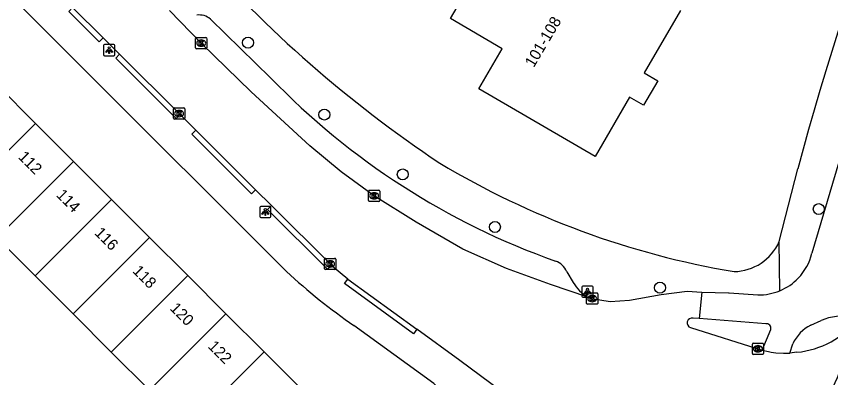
# Model space of a CAD drawing. Extents: x 159961 to 160856, y 382704 to 383353.
# Drawn here: x 160281.3 to 160353.9, y 383169.2 to 383201.5 of the extents above; entities that cross this region are included whole.
import ezdxf

# ---------------------------------------------------------------- set-up
doc = ezdxf.new("R2010")
doc.units = 0
for name, color, linetype in [('IMGEO_Boom', 7, 'Continuous'), ('IMGEO_Fietspad_open', 7, 'Continuous'), ('IMGEO_Kolk', 7, 'Continuous'), ('IMGEO_Lichtpunt', 7, 'Continuous'), ('IMGEO_Pand', 7, 'Continuous'), ('IMGEO_Pand_nummerreeks', 7, 'Continuous'), ('IMGEO_Rijbaan_lokaal_gesloten', 7, 'Continuous'), ('IMGEO_Rijbaan_lokaal_open', 7, 'Continuous'), ('IMGEO_Voetpad_open', 7, 'Continuous')]:
    doc.layers.add(name, color=color, linetype=linetype)

msp = doc.modelspace()

# ---------------------------------------------------------------- linework, layer by layer
at = {"layer": 'IMGEO_Boom'}
for centre in [(160301.954, 383199.113), (160308.756, 383192.694), (160315.74, 383187.359), (160352.813, 383184.261), (160323.955, 383182.666), (160338.661, 383177.252)]:
    msp.add_circle(centre, 0.489, dxfattribs=at)
at = {"layer": 'IMGEO_Fietspad_open'}
for points in [[(160416.978, 383298.12), (160415.622, 383296.596), (160409.982, 383290.143), (160404.533, 383283.689), (160398.866, 383276.83), (160393.529, 383269.868), (160388.714, 383263.145), (160383.615, 383255.458), (160380.25, 383250), (160379.14, 383248.2), (160375.404, 383241.384), (160371.218, 383233.388), (160367.861, 383226.24), (160364.757, 383219.002), (160361.535, 383210.673), (160358.835, 383202.785), (160352.2, 383180.324)], [(160342.396, 383176.859), (160344.757, 383176.786), (160344.828, 383176.781), (160347.397, 383176.61)], [(160348.085, 383174.03), (160342.166, 383174.495)], [(160352.112, 383173.92), (160353.037, 383174.317)], [(160347.778, 383171.678), (160348.54, 383173.52)], [(160350.236, 383171.41), (160350.49, 383172.245)]]:
    msp.add_lwpolyline(points, dxfattribs=at)
for centre, radius, start, end in [((160347.487, 383181.462), 4.849, 316.22667, 346.42206), ((160347.477, 383181.466), 4.858, 292.6591, 316.27185), ((160347.485, 383181.442), 4.832, 268.95211, 292.68392), ((160355.002, 383169.834), 4.895, 109.67973, 113.67357), ((160354.922, 383170.019), 4.694, 74.9216, 109.51357), ((160348.153, 383173.633), 0.403, 343.727, 99.74893), ((160353.802, 383170.661), 3.671, 117.40381, 154.43812)]:
    msp.add_arc(centre, radius, start, end, dxfattribs=at)
at = {"layer": 'IMGEO_Kolk'}
for p, q in [((160297.276, 383198.646), (160297.276, 383199.498)), ((160297.351, 383199.572), (160298.203, 383199.572)), ((160297.764, 383199.352), (160297.789, 383199.352)), ((160298.277, 383199.498), (160298.277, 383198.646)), ((160298.203, 383198.572), (160297.351, 383198.572)), ((160297.787, 383198.792), (160297.762, 383198.792)), ((160295.313, 383192.361), (160295.313, 383193.213)), ((160295.388, 383193.287), (160296.24, 383193.287)), ((160296.314, 383193.213), (160296.314, 383192.361)), ((160295.824, 383192.507), (160295.799, 383192.507)), ((160295.801, 383193.067), (160295.826, 383193.067)), ((160296.24, 383192.287), (160295.388, 383192.287)), ((160312.686, 383185.018), (160312.686, 383185.87)), ((160312.761, 383185.944), (160313.613, 383185.944)), ((160313.687, 383185.87), (160313.687, 383185.018)), ((160313.197, 383185.164), (160313.172, 383185.164)), ((160313.174, 383185.724), (160313.199, 383185.724)), ((160313.613, 383184.944), (160312.761, 383184.944)), ((160308.767, 383178.944), (160308.767, 383179.796)), ((160308.842, 383179.87), (160309.694, 383179.87)), ((160309.255, 383179.65), (160309.28, 383179.65)), ((160309.768, 383179.796), (160309.768, 383178.944)), ((160309.694, 383178.87), (160308.842, 383178.87)), ((160309.278, 383179.09), (160309.253, 383179.09)), ((160332.126, 383175.853), (160332.126, 383176.705)), ((160332.201, 383176.779), (160333.053, 383176.779)), ((160332.614, 383176.559), (160332.639, 383176.559)), ((160333.127, 383176.705), (160333.127, 383175.853)), ((160333.053, 383175.779), (160332.201, 383175.779)), ((160332.637, 383175.999), (160332.612, 383175.999)), ((160346.894, 383171.373), (160346.894, 383172.225)), ((160346.969, 383172.299), (160347.821, 383172.299)), ((160347.382, 383172.079), (160347.407, 383172.079)), ((160347.895, 383172.225), (160347.895, 383171.373)), ((160347.405, 383171.519), (160347.38, 383171.519)), ((160347.821, 383171.299), (160346.969, 383171.299))]:
    msp.add_line(p, q, dxfattribs=at)
for points in [[(160297.276, 383198.646), (160297.276, 383199.498)], [(160297.351, 383199.572), (160298.203, 383199.572)], [(160297.597, 383199.272), (160297.72, 383199.272), (160297.72, 383199.121), (160297.85, 383199.272), (160298.014, 383199.272), (160297.868, 383199.121), (160298.021, 383198.872), (160297.869, 383198.872), (160297.784, 383199.036), (160297.72, 383198.969), (160297.72, 383198.872), (160297.597, 383198.872), (160297.597, 383199.272)], [(160298.277, 383199.498), (160298.277, 383198.646)], [(160298.203, 383198.572), (160297.351, 383198.572)], [(160295.313, 383192.361), (160295.313, 383193.213)], [(160295.388, 383193.287), (160296.24, 383193.287)], [(160296.314, 383193.213), (160296.314, 383192.361)], [(160295.634, 383192.987), (160295.757, 383192.987), (160295.757, 383192.836), (160295.887, 383192.987), (160296.051, 383192.987), (160295.905, 383192.836), (160296.058, 383192.587), (160295.906, 383192.587), (160295.821, 383192.751), (160295.757, 383192.684), (160295.757, 383192.587), (160295.634, 383192.587), (160295.634, 383192.987)], [(160296.24, 383192.287), (160295.388, 383192.287)], [(160312.686, 383185.018), (160312.686, 383185.87)], [(160312.761, 383185.944), (160313.613, 383185.944)], [(160313.687, 383185.87), (160313.687, 383185.018)], [(160313.007, 383185.644), (160313.13, 383185.644), (160313.13, 383185.493), (160313.26, 383185.644), (160313.424, 383185.644), (160313.278, 383185.493), (160313.431, 383185.244), (160313.279, 383185.244), (160313.194, 383185.408), (160313.13, 383185.341), (160313.13, 383185.244), (160313.007, 383185.244), (160313.007, 383185.644)], [(160313.613, 383184.944), (160312.761, 383184.944)], [(160308.767, 383178.944), (160308.767, 383179.796)], [(160308.842, 383179.87), (160309.694, 383179.87)], [(160309.088, 383179.57), (160309.211, 383179.57), (160309.211, 383179.419), (160309.341, 383179.57), (160309.505, 383179.57), (160309.359, 383179.419), (160309.512, 383179.17), (160309.36, 383179.17), (160309.275, 383179.334), (160309.211, 383179.267), (160309.211, 383179.17), (160309.088, 383179.17), (160309.088, 383179.57)], [(160309.768, 383179.796), (160309.768, 383178.944)], [(160309.694, 383178.87), (160308.842, 383178.87)], [(160332.126, 383175.853), (160332.126, 383176.705)], [(160332.201, 383176.779), (160333.053, 383176.779)], [(160332.447, 383176.479), (160332.57, 383176.479), (160332.57, 383176.328), (160332.7, 383176.479), (160332.864, 383176.479), (160332.718, 383176.328), (160332.871, 383176.079), (160332.719, 383176.079), (160332.634, 383176.243), (160332.57, 383176.176), (160332.57, 383176.079), (160332.447, 383176.079), (160332.447, 383176.479)], [(160333.127, 383176.705), (160333.127, 383175.853)], [(160333.053, 383175.779), (160332.201, 383175.779)], [(160346.894, 383171.373), (160346.894, 383172.225)], [(160346.969, 383172.299), (160347.821, 383172.299)], [(160347.895, 383172.225), (160347.895, 383171.373)], [(160347.215, 383171.999), (160347.338, 383171.999), (160347.338, 383171.848), (160347.468, 383171.999), (160347.632, 383171.999), (160347.486, 383171.848), (160347.639, 383171.599), (160347.487, 383171.599), (160347.402, 383171.763), (160347.338, 383171.696), (160347.338, 383171.599), (160347.215, 383171.599), (160347.215, 383171.999)], [(160347.821, 383171.299), (160346.969, 383171.299)]]:
    msp.add_lwpolyline(points, dxfattribs=at)
for centre, start, end in [((160297.353, 383199.496), 91.55205, 178.44795), ((160297.353, 383199.496), 91.55205, 178.44795), ((160298.201, 383199.496), 1.55205, 88.44795), ((160298.201, 383199.496), 1.55205, 88.44795), ((160297.353, 383198.648), 181.55205, 268.44795), ((160297.353, 383198.648), 181.55205, 268.44795), ((160298.201, 383198.648), 271.55205, 358.44795), ((160298.201, 383198.648), 271.55205, 358.44795), ((160295.39, 383193.211), 91.55205, 178.44795), ((160295.39, 383193.211), 91.55205, 178.44795), ((160296.238, 383193.211), 1.55205, 88.44795), ((160296.238, 383193.211), 1.55205, 88.44795), ((160295.39, 383192.363), 181.55205, 268.44795), ((160295.39, 383192.363), 181.55205, 268.44795), ((160296.238, 383192.363), 271.55205, 358.44795), ((160296.238, 383192.363), 271.55205, 358.44795), ((160312.763, 383185.868), 91.55205, 178.44795), ((160312.763, 383185.868), 91.55205, 178.44795), ((160313.611, 383185.868), 1.55205, 88.44795), ((160313.611, 383185.868), 1.55205, 88.44795), ((160312.763, 383185.02), 181.55205, 268.44795), ((160312.763, 383185.02), 181.55205, 268.44795), ((160313.611, 383185.02), 271.55205, 358.44795), ((160313.611, 383185.02), 271.55205, 358.44795), ((160308.844, 383179.794), 91.55205, 178.44795), ((160308.844, 383179.794), 91.55205, 178.44795), ((160309.692, 383179.794), 1.55205, 88.44795), ((160309.692, 383179.794), 1.55205, 88.44795), ((160308.844, 383178.946), 181.55205, 268.44795), ((160308.844, 383178.946), 181.55205, 268.44795), ((160309.692, 383178.946), 271.55205, 358.44795), ((160309.692, 383178.946), 271.55205, 358.44795), ((160332.203, 383176.703), 91.55205, 178.44795), ((160332.203, 383176.703), 91.55205, 178.44795), ((160333.051, 383176.703), 1.55205, 88.44795), ((160333.051, 383176.703), 1.55205, 88.44795), ((160332.203, 383175.855), 181.55205, 268.44795), ((160332.203, 383175.855), 181.55205, 268.44795), ((160333.051, 383175.855), 271.55205, 358.44795), ((160333.051, 383175.855), 271.55205, 358.44795), ((160346.971, 383172.223), 91.55205, 178.44795), ((160346.971, 383172.223), 91.55205, 178.44795), ((160347.819, 383172.223), 1.55205, 88.44795), ((160347.819, 383172.223), 1.55205, 88.44795), ((160346.971, 383171.375), 181.55205, 268.44795), ((160346.971, 383171.375), 181.55205, 268.44795), ((160347.819, 383171.375), 271.55205, 358.44795), ((160347.819, 383171.375), 271.55205, 358.44795)]:
    msp.add_arc(centre, 0.0765, start, end, dxfattribs=at)
for centre, major_axis, ratio, start_param, end_param in [((160297.763, 383199.072), (-0.387, 0.002), 0.722429, 4.712389, 7.853982), ((160297.788, 383199.072), (-0.39, 0.002), 0.717154, 1.570796, 4.712389), ((160295.8, 383192.787), (-0.387, 0.002), 0.722429, 4.712389, 7.853982), ((160295.825, 383192.787), (-0.39, 0.002), 0.717154, 1.570796, 4.712389), ((160313.173, 383185.444), (-0.387, 0.002), 0.722429, 4.712389, 7.853982), ((160313.198, 383185.444), (-0.39, 0.002), 0.717154, 1.570796, 4.712389), ((160309.254, 383179.37), (-0.387, 0.002), 0.722429, 4.712389, 7.853982), ((160309.279, 383179.37), (-0.39, 0.002), 0.717154, 1.570796, 4.712389), ((160332.613, 383176.279), (-0.387, 0.002), 0.722429, 4.712389, 7.853982), ((160332.638, 383176.279), (-0.39, 0.002), 0.717154, 1.570796, 4.712389), ((160347.381, 383171.799), (-0.387, 0.002), 0.722429, 4.712389, 7.853982), ((160347.406, 383171.799), (-0.39, 0.002), 0.717154, 1.570796, 4.712389)]:
    msp.add_ellipse(centre, major_axis=major_axis, ratio=ratio, start_param=start_param, end_param=end_param, dxfattribs=at)
at = {"layer": 'IMGEO_Lichtpunt'}
for p, q in [((160289.982, 383198.946), (160289.174, 383198.946)), ((160289.982, 383198.946), (160289.174, 383198.946)), ((160289.08, 383198.851), (160289.08, 383198.044)), ((160289.08, 383198.851), (160289.08, 383198.044)), ((160290.076, 383198.044), (160290.076, 383198.851)), ((160290.076, 383198.044), (160290.076, 383198.851)), ((160289.174, 383197.95), (160289.982, 383197.95)), ((160289.174, 383197.95), (160289.982, 383197.95)), ((160302.997, 383184.408), (160302.997, 383183.601)), ((160302.997, 383184.408), (160302.997, 383183.601)), ((160303.899, 383184.503), (160303.091, 383184.503)), ((160303.899, 383184.503), (160303.091, 383184.503)), ((160303.993, 383183.601), (160303.993, 383184.408)), ((160303.993, 383183.601), (160303.993, 383184.408)), ((160303.091, 383183.507), (160303.899, 383183.507)), ((160303.091, 383183.507), (160303.899, 383183.507)), ((160331.707, 383177.299), (160331.707, 383176.492)), ((160331.707, 383177.299), (160331.707, 383176.492)), ((160332.609, 383177.394), (160331.801, 383177.394)), ((160332.609, 383177.394), (160331.801, 383177.394)), ((160332.703, 383176.492), (160332.703, 383177.299)), ((160332.703, 383176.492), (160332.703, 383177.299)), ((160331.801, 383176.398), (160332.609, 383176.398)), ((160331.801, 383176.398), (160332.609, 383176.398))]:
    msp.add_line(p, q, dxfattribs=at)
for points in [[(160289.454, 383198.515), (160289.493, 383198.487), (160289.305, 383198.225), (160289.267, 383198.252), (160289.454, 383198.515)], [(160289.556, 383198.467), (160289.603, 383198.467), (160289.603, 383198.145), (160289.556, 383198.145), (160289.556, 383198.467)], [(160289.666, 383198.487), (160289.704, 383198.514), (160289.891, 383198.252), (160289.852, 383198.224), (160289.666, 383198.487)], [(160303.371, 383184.072), (160303.41, 383184.044), (160303.222, 383183.782), (160303.184, 383183.809), (160303.371, 383184.072)], [(160303.473, 383184.024), (160303.52, 383184.024), (160303.52, 383183.702), (160303.473, 383183.702), (160303.473, 383184.024)], [(160303.583, 383184.044), (160303.621, 383184.071), (160303.808, 383183.809), (160303.769, 383183.781), (160303.583, 383184.044)], [(160332.081, 383176.963), (160332.12, 383176.935), (160331.932, 383176.673), (160331.894, 383176.7), (160332.081, 383176.963)], [(160332.183, 383176.915), (160332.23, 383176.915), (160332.23, 383176.593), (160332.183, 383176.593), (160332.183, 383176.915)], [(160332.293, 383176.935), (160332.331, 383176.962), (160332.518, 383176.7), (160332.479, 383176.672), (160332.293, 383176.935)]]:
    msp.add_lwpolyline(points, dxfattribs=at)
for centre in [(160289.579, 383198.649), (160303.496, 383184.206), (160332.206, 383177.097)]:
    msp.add_circle(centre, 0.0994, dxfattribs=at)
for centre, start, end in [((160289.174, 383198.851), 90, 180), ((160289.174, 383198.851), 90, 180), ((160289.982, 383198.851), 0, 90), ((160289.982, 383198.851), 0, 90), ((160289.174, 383198.044), 180, 270), ((160289.174, 383198.044), 180, 270), ((160289.982, 383198.044), 270, 0), ((160289.982, 383198.044), 270, 360), ((160303.091, 383184.408), 90, 180), ((160303.091, 383184.408), 90, 180), ((160303.899, 383184.408), 0, 90), ((160303.899, 383184.408), 0, 90), ((160303.091, 383183.601), 180, 270), ((160303.091, 383183.601), 180, 270), ((160303.899, 383183.601), 270, 0), ((160303.899, 383183.601), 270, 360), ((160331.801, 383177.299), 90, 180), ((160331.801, 383177.299), 90, 180), ((160332.609, 383177.299), 0, 90), ((160332.609, 383177.299), 0, 90), ((160331.801, 383176.492), 180, 270), ((160331.801, 383176.492), 180, 270), ((160332.609, 383176.492), 270, 0), ((160332.609, 383176.492), 270, 360)]:
    msp.add_arc(centre, 0.0946, start, end, dxfattribs=at)
at = {"layer": 'IMGEO_Pand'}
for points in [[(160340.477, 383201.99), (160337.24, 383196.428), (160338.463, 383195.716), (160337.19, 383193.53), (160335.956, 383194.249), (160332.881, 383188.966), (160322.526, 383194.992), (160324.612, 383198.576), (160320.006, 383201.256), (160323.261, 383206.849), (160327.92, 383204.138), (160330.164, 383207.993)], [(160279.626, 383195.277), (160283.011, 383191.893)], [(160276.184, 383185.088), (160283.011, 383191.893)], [(160283.011, 383191.893), (160286.405, 383188.5)], [(160279.58, 383181.693), (160286.405, 383188.5)], [(160286.405, 383188.5), (160289.798, 383185.108)], [(160289.798, 383185.108), (160282.977, 383178.298)], [(160289.798, 383185.108), (160293.184, 383181.723)], [(160282.977, 383178.298), (160279.58, 383181.693)], [(160293.184, 383181.723), (160286.366, 383174.91)], [(160293.184, 383181.723), (160296.584, 383178.324)], [(160286.366, 383174.91), (160282.977, 383178.298)], [(160289.769, 383171.508), (160296.584, 383178.324)], [(160296.584, 383178.324), (160299.977, 383174.932)], [(160289.769, 383171.508), (160286.366, 383174.91)], [(160299.977, 383174.932), (160293.165, 383168.113)], [(160299.977, 383174.932), (160303.377, 383171.533)], [(160293.165, 383168.113), (160289.769, 383171.508)], [(160296.568, 383164.711), (160303.377, 383171.533)], [(160303.377, 383171.533), (160306.77, 383168.141)]]:
    msp.add_lwpolyline(points, dxfattribs=at)
at = {"layer": 'IMGEO_Rijbaan_lokaal_gesloten'}
msp.add_arc((160228.353, 383225.777), 138.21, 334.80876, 338.15218, dxfattribs=at)
at = {"layer": 'IMGEO_Rijbaan_lokaal_open'}
for points in [[(160286.322, 383202.25), (160289.036, 383199.543)], [(160332.22, 383176.405), (160328.902, 383177.55), (160324.997, 383178.975), (160321.106, 383180.68), (160316.927, 383183.097), (160313.229, 383185.411), (160310.267, 383187.595), (160307.446, 383189.917), (160302.235, 383194.739), (160297.797, 383199.049), (160294.965, 383201.969)], [(160290.513, 383198.071), (160289.036, 383199.543)], [(160290.513, 383198.071), (160295.909, 383192.69)], [(160297.288, 383191.315), (160295.909, 383192.69)], [(160297.288, 383191.315), (160302.626, 383185.991)], [(160304.044, 383184.577), (160302.626, 383185.991)], [(160304.044, 383184.577), (160309.389, 383179.246)], [(160310.861, 383178.018), (160309.495, 383179.141), (160309.389, 383179.246)], [(160310.861, 383178.018), (160317.004, 383173.543)], [(160332.22, 383176.405), (160332.553, 383176.29), (160334.228, 383176.029), (160335.943, 383176.137), (160338.776, 383176.646), (160341.076, 383176.928), (160342.396, 383176.859)], [(160342.396, 383176.859), (160342.166, 383174.495)], [(160342.166, 383174.495), (160341.611, 383174.539)], [(160332.033, 383161.246), (160330.856, 383162.431), (160328.732, 383164.433), (160326.417, 383166.576), (160324.506, 383168.031), (160320.836, 383170.751), (160317.004, 383173.543)], [(160341.392, 383173.689), (160347.778, 383171.678)], [(160347.778, 383171.678), (160348.346, 383171.552), (160348.586, 383171.504), (160348.979, 383171.453), (160349.666, 383171.417), (160350.236, 383171.41)], [(160350.872, 383171.486), (160350.236, 383171.41)]]:
    msp.add_lwpolyline(points, dxfattribs=at)
for centre, radius, start, end in [((160341.523, 383174.109), 0.439, 78.39099, 252.71328), ((160350.061, 383179.489), 8.044, 275.78792, 321.30368)]:
    msp.add_arc(centre, radius, start, end, dxfattribs=at)
at = {"layer": 'IMGEO_Voetpad_open'}
for points in [[(160305.394, 383178.694), (160250.238, 383233.806)], [(160289.036, 383199.543), (160288.686, 383199.187), (160285.972, 383201.894), (160286.322, 383202.25)], [(160298.6, 383201.211), (160303.966, 383195.978)], [(160295.909, 383192.69), (160295.556, 383192.337), (160290.16, 383197.718), (160290.513, 383198.071)], [(160302.626, 383185.991), (160302.273, 383185.638), (160296.935, 383190.962), (160297.288, 383191.315)], [(160349.297, 383181.364), (160350.939, 383187.841)], [(160309.389, 383179.246), (160309.036, 383178.893), (160303.691, 383184.224), (160304.044, 383184.577)], [(160349.349, 383176.983), (160349.297, 383181.364)], [(160330.349, 383178.676), (160330.938, 383177.706)], [(160317.004, 383173.543), (160316.71, 383173.14), (160310.563, 383177.619), (160310.861, 383178.018)], [(160333.148, 383153.955), (160318.511, 383168.69), (160311.395, 383173.873)]]:
    msp.add_lwpolyline(points, dxfattribs=at)
for centre, radius, start, end in [((160601.538, 383120.903), 259.385, 152.19287, 165.04471), ((160380.387, 383280.344), 110.56, 221.19872, 236.29246), ((160297.618, 383200.095), 1.487, 48.6561, 99.05522), ((160351.429, 383241.773), 65.954, 223.97517, 250.4454), ((160357.767, 383252.941), 75.298, 239.03984, 260.43858), ((160345.184, 383183.188), 4.499, 270.97131, 336.08725), ((160328.797, 383178.042), 1.677, 22.23482, 70.59694), ((160340.794, 383216.613), 51.875, 226.96787, 235.4777), ((160334.189, 383179.628), 3.777, 210.585, 238.5721)]:
    msp.add_arc(centre, radius, start, end, dxfattribs=at)

# ---------------------------------------------------------------- texts
at = {"layer": 'IMGEO_Pand_nummerreeks'}
for s, rotation, p in [('101-108', 59.38652, (160327.416, 383196.834)), ('112', 315.01013, (160281.412, 383188.853)), ('114', 315.01013, (160284.809, 383185.457)), ('116', 315.01013, (160288.204, 383182.064)), ('118', 315.01013, (160291.6, 383178.67)), ('120', 315.01013, (160294.93, 383175.34)), ('122', 315.01013, (160298.32, 383171.951))]:
    msp.add_text(s, height=1, rotation=rotation, dxfattribs=at).set_placement(p)

doc.saveas('drawing.dxf')
